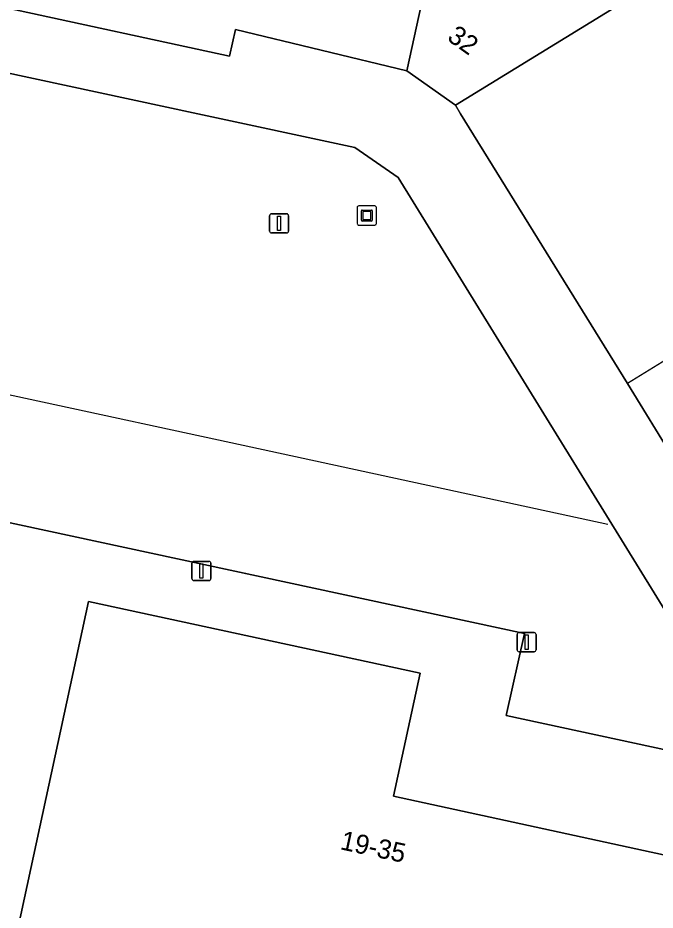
# Model space of a CAD drawing. Extents: x 161347 to 161881, y 382161 to 382804.
# Drawn here: x 161502.68 to 161535.95, y 382458.41 to 382505.01 of the extents above; entities that cross this region are included whole.
import ezdxf

# ---------------------------------------------------------------- set-up
doc = ezdxf.new("R2010")
doc.units = 0
for name, color, linetype in [('IMGEO_Erf', 7, 'Continuous'), ('IMGEO_Kunstobject', 7, 'Continuous'), ('IMGEO_Lichtmast', 7, 'Continuous'), ('IMGEO_Lijnafwatering', 7, 'Continuous'), ('IMGEO_Pand', 7, 'Continuous'), ('IMGEO_Pand_nummerreeks', 7, 'Continuous'), ('IMGEO_Pand_overbouw', 7, 'Continuous'), ('IMGEO_Voetpad_open', 7, 'Continuous')]:
    doc.layers.add(name, color=color, linetype=linetype)

msp = doc.modelspace()

# ---------------------------------------------------------------- linework, layer by layer
at = {"layer": 'IMGEO_Erf'}
for points in [[(161490.393, 382508.028), (161478.402, 382500), (161475.671, 382498.172), (161472.197, 382495.844), (161457.968, 382486.306), (161464.119, 382485.318), (161475.341, 382492.496), (161486.569, 382500), (161491.524, 382503.311), (161494.163, 382503.857), (161500, 382502.6), (161512.072, 382500), (161520.272, 382498.234), (161522.532, 382496.667), (161539.309, 382469.447), (161545.974, 382467.342), (161536.968, 382481.919), (161534.501, 382485.913), (161525.798, 382500), (161525.522, 382500.446), (161522.985, 382502.254), (161514.037, 382504.398), (161513.736, 382503.008), (161502.162, 382505.515)], [(161500, 382417.897), (161505.088, 382421.185), (161532.279, 382438.666), (161542.283, 382445.088), (161559.394, 382456.082), (161556.742, 382456.551), (161540.674, 382459.952), (161537.265, 382444.226), (161518.647, 382448.262), (161519.848, 382453.798), (161502.693, 382457.517), (161506.372, 382474.528), (161523.68, 382470.782), (161522.287, 382464.355), (161540.39, 382460.432), (161541.57, 382465.684), (161528.173, 382468.581), (161529.133, 382472.859), (161500, 382479.131)]]:
    msp.add_lwpolyline(points, dxfattribs=at)
at = {"layer": 'IMGEO_Kunstobject'}
for p, q in [((161520.399, 382495.105), (161520.399, 382494.264)), ((161520.399, 382495.105), (161520.399, 382494.264)), ((161521.315, 382495.189), (161520.474, 382495.189)), ((161521.315, 382495.189), (161520.474, 382495.189)), ((161520.613, 382494.453), (161520.613, 382494.927)), ((161520.663, 382494.977), (161521.137, 382494.977)), ((161520.693, 382494.877), (161520.693, 382494.503)), ((161521.087, 382494.897), (161520.713, 382494.897)), ((161521.107, 382494.503), (161521.107, 382494.877)), ((161521.187, 382494.927), (161521.187, 382494.453)), ((161521.399, 382494.273), (161521.399, 382495.114)), ((161521.399, 382494.273), (161521.399, 382495.114)), ((161521.137, 382494.403), (161520.663, 382494.403)), ((161520.713, 382494.483), (161521.087, 382494.483)), ((161520.483, 382494.189), (161521.324, 382494.189)), ((161520.483, 382494.189), (161521.324, 382494.189))]:
    msp.add_line(p, q, dxfattribs=at)
for centre, radius, start, end in [((161520.477, 382495.111), 0.0779, 92.4484, 184.2845), ((161520.477, 382495.111), 0.0779, 92.4484, 184.2845), ((161520.663, 382494.927), 0.05, 90, 180), ((161520.713, 382494.877), 0.02, 90, 180), ((161521.087, 382494.877), 0.02, 360, 90), ((161521.137, 382494.927), 0.05, 360, 90), ((161521.321, 382495.111), 0.0779, 2.4484, 94.2845), ((161521.321, 382495.111), 0.0779, 2.4484, 94.2845), ((161520.663, 382494.453), 0.05, 180, 270), ((161520.713, 382494.503), 0.02, 180, 270), ((161521.087, 382494.503), 0.02, 270, 0), ((161521.137, 382494.453), 0.05, 270, 0), ((161520.477, 382494.267), 0.0779, 182.4484, 274.2845), ((161520.477, 382494.267), 0.0779, 182.4484, 274.2845), ((161521.321, 382494.267), 0.0779, 272.4484, 4.2845), ((161521.321, 382494.267), 0.0779, 272.4484, 4.2845)]:
    msp.add_arc(centre, radius, start, end, dxfattribs=at)
at = {"layer": 'IMGEO_Lichtmast'}
for p, q in [((161515.823, 382493.879), (161515.823, 382494.679)), ((161515.823, 382494.679), (161515.823, 382493.879)), ((161515.923, 382494.779), (161516.713, 382494.779)), ((161516.713, 382494.779), (161515.923, 382494.779)), ((161516.813, 382494.679), (161516.813, 382493.879)), ((161516.813, 382493.879), (161516.813, 382494.679)), ((161516.713, 382493.779), (161515.923, 382493.779)), ((161515.923, 382493.779), (161516.713, 382493.779)), ((161511.769, 382475.724), (161511.769, 382476.524)), ((161511.769, 382476.524), (161511.769, 382475.724)), ((161511.869, 382476.624), (161512.659, 382476.624)), ((161512.659, 382476.624), (161511.869, 382476.624)), ((161512.759, 382476.524), (161512.759, 382475.724)), ((161512.759, 382475.724), (161512.759, 382476.524)), ((161512.659, 382475.624), (161511.869, 382475.624)), ((161511.869, 382475.624), (161512.659, 382475.624)), ((161528.747, 382472.004), (161528.747, 382472.804)), ((161528.747, 382472.804), (161528.747, 382472.004)), ((161528.847, 382472.904), (161529.637, 382472.904)), ((161529.637, 382472.904), (161528.847, 382472.904)), ((161529.737, 382472.804), (161529.737, 382472.004)), ((161529.737, 382472.004), (161529.737, 382472.804)), ((161529.637, 382471.904), (161528.847, 382471.904)), ((161528.847, 382471.904), (161529.637, 382471.904))]:
    msp.add_line(p, q, dxfattribs=at)
for points in [[(161516.243, 382494.654), (161516.393, 382494.654), (161516.393, 382493.904), (161516.243, 382493.904), (161516.243, 382494.654)], [(161512.189, 382476.499), (161512.339, 382476.499), (161512.339, 382475.749), (161512.189, 382475.749), (161512.189, 382476.499)], [(161529.167, 382472.779), (161529.317, 382472.779), (161529.317, 382472.029), (161529.167, 382472.029), (161529.167, 382472.779)]]:
    msp.add_lwpolyline(points, dxfattribs=at)
for centre, start, end in [((161515.923, 382494.679), 90, 180), ((161515.923, 382494.679), 90, 180), ((161516.713, 382494.679), 0, 90), ((161516.713, 382494.679), 360, 90), ((161515.923, 382493.879), 180, 270), ((161515.923, 382493.879), 180, 270), ((161516.713, 382493.879), 270, 0), ((161516.713, 382493.879), 270, 0), ((161511.869, 382476.524), 90, 180), ((161511.869, 382476.524), 90, 180), ((161512.659, 382476.524), 0, 90), ((161512.659, 382476.524), 360, 90), ((161511.869, 382475.724), 180, 270), ((161511.869, 382475.724), 180, 270), ((161512.659, 382475.724), 270, 0), ((161512.659, 382475.724), 270, 0), ((161528.847, 382472.804), 90, 180), ((161528.847, 382472.804), 90, 180), ((161529.637, 382472.804), 0, 90), ((161529.637, 382472.804), 360, 90), ((161528.847, 382472.004), 180, 270), ((161528.847, 382472.004), 180, 270), ((161529.637, 382472.004), 270, 0), ((161529.637, 382472.004), 270, 0)]:
    msp.add_arc(centre, 0.1, start, end, dxfattribs=at)
at = {"layer": 'IMGEO_Lijnafwatering'}
for points in [[(161513.801, 382482.815), (161494.119, 382487.072)], [(161533.484, 382478.557), (161513.801, 382482.815)]]:
    msp.add_lwpolyline(points, dxfattribs=at)
at = {"layer": 'IMGEO_Pand'}
for points in [[(161493.46, 382508.654), (161500, 382507.249), (161502.425, 382506.727), (161502.162, 382505.515), (161513.736, 382503.008), (161514.037, 382504.398), (161522.985, 382502.254), (161525.404, 382513.316), (161526.419, 382517.967), (161517.425, 382519.928), (161517.696, 382521.116), (161514.593, 382521.824), (161514.317, 382520.616), (161508.929, 382521.808), (161509.21, 382522.996), (161506.08, 382523.629), (161505.8, 382522.442), (161500, 382523.705), (161496.857, 382524.389), (161495.848, 382519.776)], [(161540.674, 382459.952), (161540.732, 382460.291), (161540.39, 382460.432), (161522.287, 382464.355), (161523.68, 382470.782), (161506.372, 382474.528), (161502.693, 382457.517), (161519.848, 382453.798), (161518.647, 382448.262), (161537.265, 382444.226)]]:
    msp.add_lwpolyline(points, close=True, dxfattribs=at)
for points in [[(161527.687, 382512.691), (161525.404, 382513.316), (161522.985, 382502.254), (161525.522, 382500.446), (161535.204, 382506.4)], [(161548.297, 382494.301), (161544.762, 382500), (161539.238, 382508.903), (161535.204, 382506.4), (161525.522, 382500.446), (161525.798, 382500), (161534.501, 382485.913), (161536.968, 382481.919), (161545.974, 382467.342), (161551.092, 382470.489), (161559.71, 382475.789), (161550.708, 382490.406)]]:
    msp.add_lwpolyline(points, dxfattribs=at)
at = {"layer": 'IMGEO_Pand_overbouw'}
msp.add_lwpolyline([(161534.501, 382485.913), (161536.968, 382481.919), (161539.014, 382483.183), (161536.547, 382487.177)], close=True, dxfattribs=at)
at = {"layer": 'IMGEO_Voetpad_open'}
msp.add_lwpolyline([(161500, 382479.131), (161529.133, 382472.859), (161528.173, 382468.581), (161541.57, 382465.684), (161557.97, 382462.132), (161557.899, 382461.771), (161556.802, 382456.914), (161556.742, 382456.551), (161559.394, 382456.082), (161566.563, 382460.64), (161551.092, 382470.489), (161545.974, 382467.342), (161539.309, 382469.447), (161522.532, 382496.667), (161520.272, 382498.234), (161512.072, 382500), (161500, 382502.6)], dxfattribs=at)

# ---------------------------------------------------------------- texts
at = {"layer": 'IMGEO_Pand_nummerreeks'}
for s, rotation, p in [('32', 324.5243, (161525.04, 382503.884)), ('19-35', 347.8232, (161519.465, 382461.592))]:
    msp.add_text(s, height=1, rotation=rotation, dxfattribs=at).set_placement(p)

doc.saveas('drawing.dxf')
